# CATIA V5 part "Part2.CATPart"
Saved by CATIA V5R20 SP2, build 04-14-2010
Part number: Part2
Bounding box of the stored display mesh (mm): x -35 to 60, y 622.55 to 722.55, z -27.39 to 27.39
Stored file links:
  E:\CATIA\New folder\Part2.CATPart
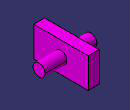
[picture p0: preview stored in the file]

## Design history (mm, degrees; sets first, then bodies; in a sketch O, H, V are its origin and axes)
Body1 (main body)
  DatumCurve1
  DatumCurve2
  Sketch1 on yz-plane, origin (0, 0, 0), H (0, 1, 0), V (0, 0, 1)
    line L1 (622.55, 27.39) -> (722.55, 27.39)
    line L2 (722.55, 27.39) -> (722.55, -27.39)
    line L3 (722.55, -27.39) -> (622.55, -27.39)
    line L4 (622.55, -27.39) -> (622.55, 27.39)
  Pad1: profile Sketch1, direction (1, 0, 0), length 20
  Sketch2 on end face of Pad1, origin (20, 0, 0), H (0, 1, 0), V (0, 0, 1)
    circle A1 centre (672.55, 0) radius 11
  Pad2: profile Sketch2, direction (1, 0, 0), length 40, opposite side length 55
